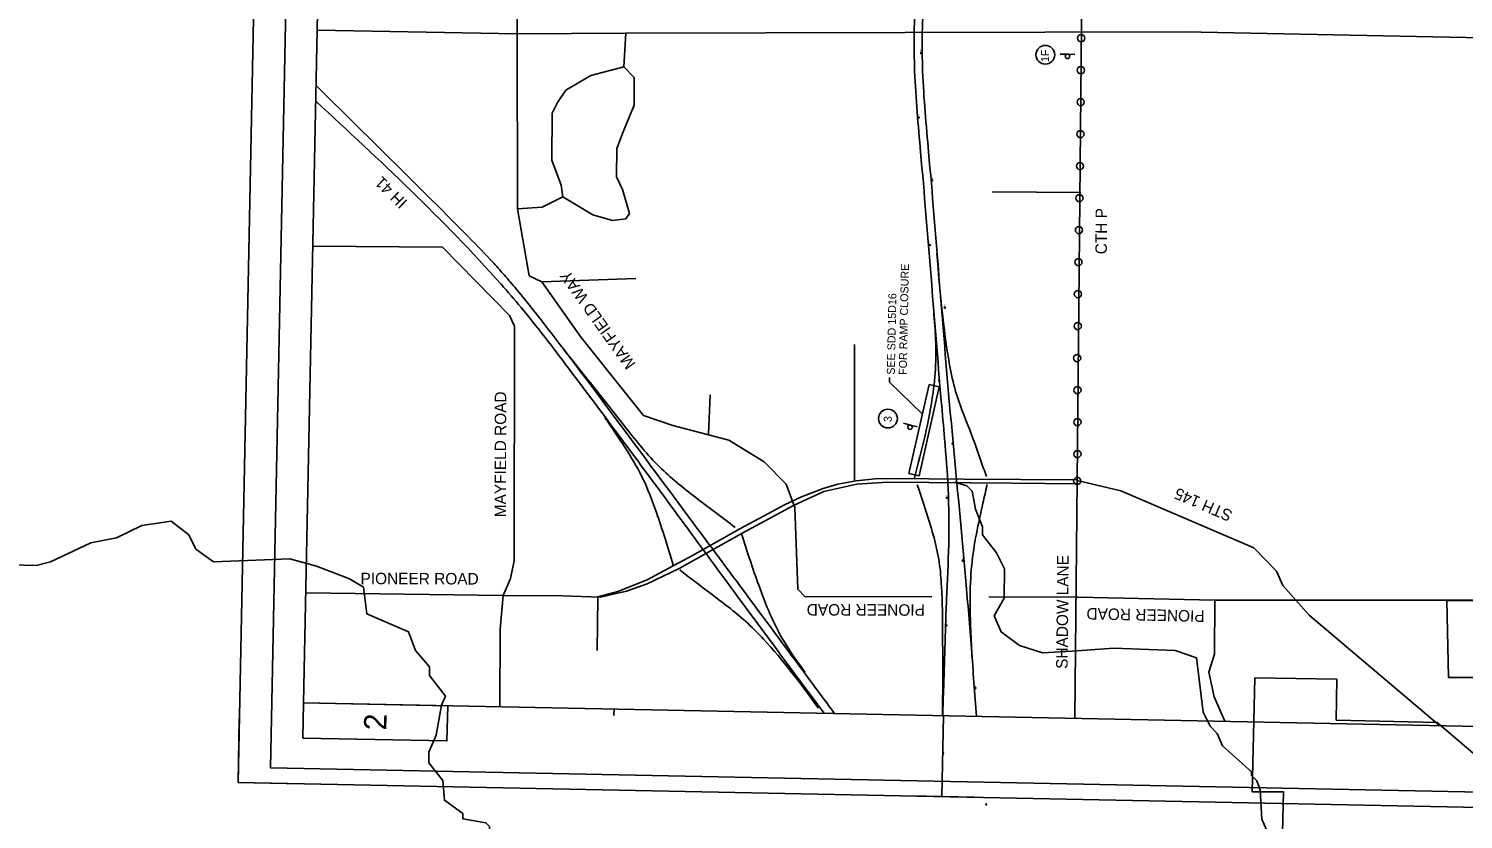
# Model space of a CAD drawing. Extents: x 331323 to 388339, y 121519 to 205315.
# Drawn here: x 352829 to 366276, y 130182 to 137595 of the extents above; entities that cross this region are included whole.
import ezdxf

# ---------------------------------------------------------------- set-up
doc = ezdxf.new("R2010")
doc.units = 0
for name, color, linetype in [('CA-TEXT', 7, 'Continuous'), ('CE-TOPO-CONC-SLAB', 7, 'Continuous'), ('E_SOIL_BORE1 [KAPUR_CADDS_LEVELS]', 7, 'Continuous'), ('E_SOIL_BORE2 [KAPUR_CADDS_LEVELS]', 7, 'Continuous'), ('Level 2', 7, 'Continuous'), ('Level 21', 7, 'Continuous'), ('Level 3', 7, 'Continuous'), ('Level 4', 7, 'Continuous'), ('Level 57', 7, 'Continuous'), ('P_MARK', 7, 'Continuous'), ('P_RDWY_Text', 7, 'Continuous'), ('P_TC', 7, 'Continuous'), ('PLT_Sheet_Border', 7, 'Continuous'), ('PLT_Sheet_Info', 7, 'Continuous'), ('SIGNS-POLES', 7, 'Continuous')]:
    doc.layers.add(name, color=color, linetype=linetype)

msp = doc.modelspace()

# ---------------------------------------------------------------- linework, layer by layer
at = {"layer": 'CA-TEXT'}
for p, q in [((360898, 134282), (360898, 134325)), ((361206, 133982), (360898, 134282))]:
    msp.add_line(p, q, dxfattribs=at)
for centre in [(362358, 137350), (360883, 133939)]:
    msp.add_circle(centre, 88, dxfattribs=at)
at = {"layer": 'CE-TOPO-CONC-SLAB'}
for centre in [(362694, 137506), (362691, 137206), (362689, 136906), (362687, 136606), (362683, 136306), (362678, 136006), (362673, 135706), (362668, 135406), (362663, 135106), (362662, 134806), (362656, 134506), (362659, 134206), (362659, 133906), (362659, 133606), (362657, 133355)]:
    msp.add_circle(centre, 33.5, dxfattribs=at)
at = {"layer": 'Level 2'}
msp.add_lwpolyline([(362657, 133360), (363065, 133262), (364311, 132726), (364526, 132507), (364583, 132373), (364830, 132096), (366052, 131060)], dxfattribs=at)
for points in [[(361414, 133750), (361383, 134102), (361189, 136437), (361133, 137194), (361147, 137923), (361252, 138764), (361336, 139462), (361400, 139990)], [(361712, 131147), (361665, 131783), (361613, 132419), (361458, 134102), (361264, 136437), (361208, 137193), (361223, 137922), (361327, 138763), (361411, 139462), (361475, 139988)], [(355523, 137061), (356920, 135674), (357158, 135428), (357273, 135300), (357385, 135170), (357696, 134781), (358305, 133974), (358999, 133039), (360250, 131353), (360382, 131174)], [(360285, 131176), (359489, 132250), (358879, 133080), (357889, 134411), (357444, 134981), (357256, 135199), (355520, 136915)], [(361805, 133396), (361649, 133834), (361517, 134194), (361461, 134443), (361342, 135488)], [(361306, 135014), (361331, 134477), (361306, 134184), (361132, 133383)], [(359452, 132917), (359056, 133218), (358722, 133506), (358408, 133877), (357848, 134581)], [(358229, 133950), (358416, 133670), (358577, 133393), (358713, 133057), (358871, 132569)], [(361414, 133750), (361447, 133280), (361452, 132761), (361432, 132242), (361414, 131698), (361396, 131154)], [(361158, 133317), (361307, 132849), (361359, 132621), (361374, 132505), (361383, 132388), (361391, 132223), (361394, 132058), (361395, 131154)], [(361672, 131684), (361653, 132234), (361668, 132565), (361773, 133147), (361813, 133322)], [(360104, 131562), (359906, 131854), (359672, 132376), (359512, 132851)], [(358931, 132520), (359213, 132305), (359550, 132036), (359716, 131872), (360232, 131224)]]:
    msp.add_spline(points, degree=3, dxfattribs=at)
at = {"layer": 'Level 21'}
msp.add_lwpolyline([(377063, 130598), (375063, 130636), (375076, 132102), (370943, 132185), (370895, 130740), (370392, 130742), (370319, 126443), (367795, 126431), (367808, 132231), (366120, 132233), (366136, 131513), (366392, 131512), (366390, 130783), (366031, 131091), (365085, 131112), (365090, 131495), (364323, 131507), (364297, 130440), (364589, 130440), (364573, 129673), (363929, 129678), (363912, 128375), (362626, 128410), (362594, 121807)], dxfattribs=at)
at = {"layer": 'Level 3'}
msp.add_lwpolyline([(362673, 142845), (362696, 137641), (362657, 133360)], dxfattribs=at)
at = {"layer": 'Level 4'}
for p, q in [((361860, 136065), (362690, 136059)), ((360569, 133362), (360568, 134634)), ((359200, 133793), (359216, 134161)), ((358163, 132260), (358158, 131766))]:
    msp.add_line(p, q, dxfattribs=at)
for points in [[(357407, 148129), (357408, 137547)], [(355533, 137580), (357408, 137547)], [(358426, 137554), (363663, 137565), (367234, 137492)], [(357408, 137547), (358426, 137554)], [(357408, 137547), (357410, 135905)], [(358406, 137238), (358426, 137554)], [(357836, 136018), (357820, 136126), (357731, 136361), (357735, 136802), (357786, 136902), (357862, 137018), (358097, 137157), (358406, 137238)], [(357836, 136018), (358118, 135849), (358301, 135797), (358426, 135813), (358460, 135862), (358395, 136088), (358338, 136205), (358341, 136472), (358366, 136538), (358400, 136629), (358503, 136879), (358505, 137137), (358406, 137238)], [(357410, 135905), (357643, 135920), (357836, 136018)], [(357410, 135905), (357521, 135279), (357637, 135220)], [(355492, 135556), (356706, 135545), (357334, 134906), (357383, 134805), (357379, 132605), (357344, 132439), (357276, 132281)], [(357637, 135220), (358521, 135253)], [(357637, 135220), (358007, 134700), (358428, 134171), (358593, 133969), (358867, 133875), (359391, 133737), (359723, 133534), (359929, 133324), (360011, 133106), (360037, 132340), (360103, 132272), (361293, 132269)], [(357276, 132281), (357836, 132276), (358185, 132264), (358433, 132320), (358627, 132391), (358925, 132532), (359524, 132868), (360005, 133126), (360281, 133254), (360592, 133324), (360880, 133342), (362050, 133333), (362657, 133328)], [(362658, 133365), (361593, 133372), (360937, 133376), (360764, 133375), (360586, 133356), (360414, 133323), (360275, 133283), (360072, 133206), (359920, 133134), (359717, 133023), (359495, 132906), (359051, 132655), (358743, 132490), (358625, 132428), (358351, 132318), (358164, 132268)], [(362636, 131129), (362657, 133360)], [(355427, 132304), (357276, 132281)], [(357276, 132281), (357248, 131965), (357245, 131237)], [(361829, 132268), (362664, 132266)], [(362664, 132266), (363948, 132237)], [(363948, 132237), (363943, 131729), (363891, 131563), (363939, 131329), (364039, 131101)], [(363948, 132237), (367128, 132236)]]:
    msp.add_lwpolyline(points, dxfattribs=at)
at = {"layer": 'Level 57'}
for points in [[(361506, 133343), (361622, 133309), (361672, 133258), (361704, 133091), (361769, 132924), (361768, 132849), (361900, 132681), (361974, 132530), (361971, 132255), (361878, 132090), (361943, 131939), (362117, 131812), (362333, 131744), (362609, 131758), (363001, 131788), (363576, 131766), (363776, 131697), (363838, 131188), (363903, 131054), (363969, 130987), (364018, 130870), (364291, 130626), (364291, 130593), (364341, 130542), (364373, 130459), (364387, 130183), (364469, 129999)], [(351966, 132588), (352900, 132562), (353034, 132595), (353411, 132775), (353653, 132822), (353888, 132937), (354163, 132976), (354329, 132850), (354394, 132716), (354560, 132597), (355278, 132624), (355527, 132555), (355835, 132436), (355967, 132360), (355998, 132109), (356389, 131939), (356454, 131764), (356586, 131612), (356585, 131529), (356734, 131336), (356699, 131253), (356647, 130970), (356579, 130812), (356578, 130712), (356710, 130545), (356725, 130361), (356899, 130235), (356898, 130185)], [(356898, 130185), (357115, 130149), (357148, 130116), (357162, 129882), (357237, 129815), (357470, 129829), (357720, 129827), (358061, 129716), (358317, 129413), (358466, 129329), (358908, 129266), (359024, 129182), (359258, 129196), (359783, 129208), (361568, 129209)]]:
    msp.add_lwpolyline(points, dxfattribs=at)
at = {"layer": 'P_MARK'}
for p, q in [((361188, 137365), (361198, 137365)), ((361193, 137370), (361193, 137360)), ((361168, 136761), (361178, 136761)), ((361173, 136766), (361173, 136756)), ((361291, 136173), (361301, 136173)), ((361296, 136178), (361296, 136168)), ((361273, 135566), (361283, 135566)), ((361278, 135571), (361278, 135561)), ((361411, 134979), (361421, 134979)), ((361416, 134984), (361416, 134974)), ((361358, 134294), (361368, 134294)), ((361363, 134299), (361363, 134289)), ((361484, 133704), (361494, 133704)), ((361489, 133709), (361489, 133699)), ((361430, 133197), (361440, 133197)), ((361435, 133202), (361435, 133192)), ((361580, 132607), (361590, 132607)), ((361585, 132612), (361585, 132602)), ((361427, 132000), (361437, 132000)), ((361432, 132005), (361432, 131995)), ((361697, 131413), (361707, 131413)), ((361702, 131418), (361702, 131408)), ((361396, 130801), (361406, 130801)), ((361401, 130806), (361401, 130796)), ((361799, 130321), (361809, 130321)), ((361804, 130326), (361804, 130316))]:
    msp.add_line(p, q, dxfattribs=at)
for centre in [(361193, 137365), (361173, 136761), (361296, 136173), (361278, 135566), (361416, 134979), (361363, 134294), (361489, 133704), (361435, 133197), (361585, 132607), (361432, 132000), (361702, 131413), (361401, 130801), (361804, 130321)]:
    msp.add_circle(centre, 5, dxfattribs=at)
for centre, radius, start, end in [((361193, 137365), 4.5, 89.9869, 179.9869), ((361193, 137365), 4, 89.9869, 179.9869), ((361193, 137365), 3.5, 89.9869, 179.9869), ((361193, 137365), 3, 89.9869, 179.9869), ((361193, 137365), 2.5, 89.9869, 179.9869), ((361193, 137365), 2, 89.9869, 179.9869), ((361193, 137365), 1.5, 89.9869, 179.9869), ((361193, 137365), 1, 89.9869, 179.9869), ((361193, 137365), 0.5, 89.9869, 179.9869), ((361193, 137365), 4.5, 269.9869, 359.9869), ((361193, 137365), 4, 269.9869, 359.9869), ((361193, 137365), 3.5, 269.9869, 359.9869), ((361193, 137365), 3, 269.9869, 359.9869), ((361193, 137365), 2.5, 269.9869, 359.9869), ((361193, 137365), 2, 269.9869, 359.9869), ((361193, 137365), 1.5, 269.9869, 359.9869), ((361193, 137365), 1, 269.9869, 359.9869), ((361193, 137365), 0.5, 269.9869, 359.9869), ((361173, 136761), 4.5, 89.9869, 179.9869), ((361173, 136761), 4, 89.9869, 179.9869), ((361173, 136761), 3.5, 89.9869, 179.9869), ((361173, 136761), 3, 89.9869, 179.9869), ((361173, 136761), 2.5, 89.9869, 179.9869), ((361173, 136761), 2, 89.9869, 179.9869), ((361173, 136761), 1.5, 89.9869, 179.9869), ((361173, 136761), 1, 89.9869, 179.9869), ((361173, 136761), 0.5, 89.9869, 179.9869), ((361173, 136761), 4.5, 269.9869, 359.9869), ((361173, 136761), 4, 269.9869, 359.9869), ((361173, 136761), 3.5, 269.9869, 359.9869), ((361173, 136761), 3, 269.9869, 359.9869), ((361173, 136761), 2.5, 269.9869, 359.9869), ((361173, 136761), 2, 269.9869, 359.9869), ((361173, 136761), 1.5, 269.9869, 359.9869), ((361173, 136761), 1, 269.9869, 359.9869), ((361173, 136761), 0.5, 269.9869, 359.9869), ((361296, 136173), 4.5, 89.9869, 179.9869), ((361296, 136173), 4, 89.9869, 179.9869), ((361296, 136173), 3.5, 89.9869, 179.9869), ((361296, 136173), 3, 89.9869, 179.9869), ((361296, 136173), 2.5, 89.9869, 179.9869), ((361296, 136173), 2, 89.9869, 179.9869), ((361296, 136173), 1.5, 89.9869, 179.9869), ((361296, 136173), 1, 89.9869, 179.9869), ((361296, 136173), 0.5, 89.9869, 179.9869), ((361296, 136173), 4.5, 269.9869, 359.9869), ((361296, 136173), 4, 269.9869, 359.9869), ((361296, 136173), 3.5, 269.9869, 359.9869), ((361296, 136173), 3, 269.9869, 359.9869), ((361296, 136173), 2.5, 269.9869, 359.9869), ((361296, 136173), 2, 269.9869, 359.9869), ((361296, 136173), 1.5, 269.9869, 359.9869), ((361296, 136173), 1, 269.9869, 359.9869), ((361296, 136173), 0.5, 269.9869, 359.9869), ((361278, 135566), 4.5, 89.9869, 179.9869), ((361278, 135566), 4, 89.9869, 179.9869), ((361278, 135566), 3.5, 89.9869, 179.9869), ((361278, 135566), 3, 89.9869, 179.9869), ((361278, 135566), 2.5, 89.9869, 179.9869), ((361278, 135566), 2, 89.9869, 179.9869), ((361278, 135566), 1.5, 89.9869, 179.9869), ((361278, 135566), 1, 89.9869, 179.9869), ((361278, 135566), 0.5, 89.9869, 179.9869), ((361278, 135566), 4.5, 269.9869, 359.9869), ((361278, 135566), 4, 269.9869, 359.9869), ((361278, 135566), 3.5, 269.9869, 359.9869), ((361278, 135566), 3, 269.9869, 359.9869), ((361278, 135566), 2.5, 269.9869, 359.9869), ((361278, 135566), 2, 269.9869, 359.9869), ((361278, 135566), 1.5, 269.9869, 359.9869), ((361278, 135566), 1, 269.9869, 359.9869), ((361278, 135566), 0.5, 269.9869, 359.9869), ((361416, 134979), 4.5, 89.9869, 179.9869), ((361416, 134979), 4, 89.9869, 179.9869), ((361416, 134979), 3.5, 89.9869, 179.9869), ((361416, 134979), 3, 89.9869, 179.9869), ((361416, 134979), 2.5, 89.9869, 179.9869), ((361416, 134979), 2, 89.9869, 179.9869), ((361416, 134979), 1.5, 89.9869, 179.9869), ((361416, 134979), 1, 89.9869, 179.9869), ((361416, 134979), 0.5, 89.9869, 179.9869), ((361416, 134979), 4.5, 269.9869, 359.9869), ((361416, 134979), 4, 269.9869, 359.9869), ((361416, 134979), 3.5, 269.9869, 359.9869), ((361416, 134979), 3, 269.9869, 359.9869), ((361416, 134979), 2.5, 269.9869, 359.9869), ((361416, 134979), 2, 269.9869, 359.9869), ((361416, 134979), 1.5, 269.9869, 359.9869), ((361416, 134979), 1, 269.9869, 359.9869), ((361416, 134979), 0.5, 269.9869, 359.9869), ((361363, 134294), 4.5, 89.9869, 179.9869), ((361363, 134294), 4, 89.9869, 179.9869), ((361363, 134294), 3.5, 89.9869, 179.9869), ((361363, 134294), 3, 89.9869, 179.9869), ((361363, 134294), 2.5, 89.9869, 179.9869), ((361363, 134294), 2, 89.9869, 179.9869), ((361363, 134294), 1.5, 89.9869, 179.9869), ((361363, 134294), 1, 89.9869, 179.9869), ((361363, 134294), 0.5, 89.9869, 179.9869), ((361363, 134294), 4.5, 269.9869, 359.9869), ((361363, 134294), 4, 269.9869, 359.9869), ((361363, 134294), 3.5, 269.9869, 359.9869), ((361363, 134294), 3, 269.9869, 359.9869), ((361363, 134294), 2.5, 269.9869, 359.9869), ((361363, 134294), 2, 269.9869, 359.9869), ((361363, 134294), 1.5, 269.9869, 359.9869), ((361363, 134294), 1, 269.9869, 359.9869), ((361363, 134294), 0.5, 269.9869, 359.9869), ((361489, 133704), 4.5, 89.9869, 179.9869), ((361489, 133704), 4, 89.9869, 179.9869), ((361489, 133704), 3.5, 89.9869, 179.9869), ((361489, 133704), 3, 89.9869, 179.9869), ((361489, 133704), 2.5, 89.9869, 179.9869), ((361489, 133704), 2, 89.9869, 179.9869), ((361489, 133704), 1.5, 89.9869, 179.9869), ((361489, 133704), 1, 89.9869, 179.9869), ((361489, 133704), 0.5, 89.9869, 179.9869), ((361489, 133704), 4.5, 269.9869, 359.9869), ((361489, 133704), 4, 269.9869, 359.9869), ((361489, 133704), 3.5, 269.9869, 359.9869), ((361489, 133704), 3, 269.9869, 359.9869), ((361489, 133704), 2.5, 269.9869, 359.9869), ((361489, 133704), 2, 269.9869, 359.9869), ((361489, 133704), 1.5, 269.9869, 359.9869), ((361489, 133704), 1, 269.9869, 359.9869), ((361489, 133704), 0.5, 269.9869, 359.9869), ((361435, 133197), 4.5, 89.9869, 179.9869), ((361435, 133197), 4, 89.9869, 179.9869), ((361435, 133197), 3.5, 89.9869, 179.9869), ((361435, 133197), 3, 89.9869, 179.9869), ((361435, 133197), 2.5, 89.9869, 179.9869), ((361435, 133197), 2, 89.9869, 179.9869), ((361435, 133197), 1.5, 89.9869, 179.9869), ((361435, 133197), 1, 89.9869, 179.9869), ((361435, 133197), 0.5, 89.9869, 179.9869), ((361435, 133197), 4.5, 269.9869, 359.9869), ((361435, 133197), 4, 269.9869, 359.9869), ((361435, 133197), 3.5, 269.9869, 359.9869), ((361435, 133197), 3, 269.9869, 359.9869), ((361435, 133197), 2.5, 269.9869, 359.9869), ((361435, 133197), 2, 269.9869, 359.9869), ((361435, 133197), 1.5, 269.9869, 359.9869), ((361435, 133197), 1, 269.9869, 359.9869), ((361435, 133197), 0.5, 269.9869, 359.9869), ((361585, 132607), 4.5, 89.9869, 179.9869), ((361585, 132607), 4, 89.9869, 179.9869), ((361585, 132607), 3.5, 89.9869, 179.9869), ((361585, 132607), 3, 89.9869, 179.9869), ((361585, 132607), 2.5, 89.9869, 179.9869), ((361585, 132607), 2, 89.9869, 179.9869), ((361585, 132607), 1.5, 89.9869, 179.9869), ((361585, 132607), 1, 89.9869, 179.9869), ((361585, 132607), 0.5, 89.9869, 179.9869), ((361585, 132607), 4.5, 269.9869, 359.9869), ((361585, 132607), 4, 269.9869, 359.9869), ((361585, 132607), 3.5, 269.9869, 359.9869), ((361585, 132607), 3, 269.9869, 359.9869), ((361585, 132607), 2.5, 269.9869, 359.9869), ((361585, 132607), 2, 269.9869, 359.9869), ((361585, 132607), 1.5, 269.9869, 359.9869), ((361585, 132607), 1, 269.9869, 359.9869), ((361585, 132607), 0.5, 269.9869, 359.9869), ((361432, 132000), 4.5, 89.9869, 179.9869), ((361432, 132000), 4, 89.9869, 179.9869), ((361432, 132000), 3.5, 89.9869, 179.9869), ((361432, 132000), 3, 89.9869, 179.9869), ((361432, 132000), 2.5, 89.9869, 179.9869), ((361432, 132000), 2, 89.9869, 179.9869), ((361432, 132000), 1.5, 89.9869, 179.9869), ((361432, 132000), 1, 89.9869, 179.9869), ((361432, 132000), 0.5, 89.9869, 179.9869), ((361432, 132000), 4.5, 269.9869, 359.9869), ((361432, 132000), 4, 269.9869, 359.9869), ((361432, 132000), 3.5, 269.9869, 359.9869), ((361432, 132000), 3, 269.9869, 359.9869), ((361432, 132000), 2.5, 269.9869, 359.9869), ((361432, 132000), 2, 269.9869, 359.9869), ((361432, 132000), 1.5, 269.9869, 359.9869), ((361432, 132000), 1, 269.9869, 359.9869), ((361432, 132000), 0.5, 269.9869, 359.9869), ((361702, 131413), 4.5, 89.9869, 179.9869), ((361702, 131413), 4, 89.9869, 179.9869), ((361702, 131413), 3.5, 89.9869, 179.9869), ((361702, 131413), 3, 89.9869, 179.9869), ((361702, 131413), 2.5, 89.9869, 179.9869), ((361702, 131413), 2, 89.9869, 179.9869), ((361702, 131413), 1.5, 89.9869, 179.9869), ((361702, 131413), 1, 89.9869, 179.9869), ((361702, 131413), 4.5, 269.9869, 359.9869), ((361702, 131413), 4, 269.9869, 359.9869), ((361702, 131413), 3.5, 269.9869, 359.9869), ((361702, 131413), 3, 269.9869, 359.9869), ((361702, 131413), 2.5, 269.9869, 359.9869), ((361702, 131413), 2, 269.9869, 359.9869), ((361702, 131413), 1.5, 269.9869, 359.9869), ((361702, 131413), 1, 269.9869, 359.9869), ((361702, 131413), 0.5, 269.9869, 359.9869), ((361702, 131413), 0.5, 89.9869, 179.9869), ((361401, 130801), 4.5, 89.9869, 179.9869), ((361401, 130801), 4, 89.9869, 179.9869), ((361401, 130801), 3.5, 89.9869, 179.9869), ((361401, 130801), 3, 89.9869, 179.9869), ((361401, 130801), 2.5, 89.9869, 179.9869), ((361401, 130801), 2, 89.9869, 179.9869), ((361401, 130801), 1.5, 89.9869, 179.9869), ((361401, 130801), 1, 89.9869, 179.9869), ((361401, 130801), 0.5, 89.9869, 179.9869), ((361401, 130801), 4.5, 269.9869, 359.9869), ((361401, 130801), 4, 269.9869, 359.9869), ((361401, 130801), 3.5, 269.9869, 359.9869), ((361401, 130801), 3, 269.9869, 359.9869), ((361401, 130801), 2.5, 269.9869, 359.9869), ((361401, 130801), 2, 269.9869, 359.9869), ((361401, 130801), 1.5, 269.9869, 359.9869), ((361401, 130801), 1, 269.9869, 359.9869), ((361401, 130801), 0.5, 269.9869, 359.9869), ((361804, 130321), 4.5, 89.9869, 179.9869), ((361804, 130321), 4, 89.9869, 179.9869), ((361804, 130321), 3.5, 89.9869, 179.9869), ((361804, 130321), 3, 89.9869, 179.9869), ((361804, 130321), 2.5, 89.9869, 179.9869), ((361804, 130321), 2, 89.9869, 179.9869), ((361804, 130321), 1.5, 89.9869, 179.9869), ((361804, 130321), 1, 89.9869, 179.9869), ((361804, 130321), 4.5, 269.9869, 359.9869), ((361804, 130321), 4, 269.9869, 359.9869), ((361804, 130321), 3.5, 269.9869, 359.9869), ((361804, 130321), 3, 269.9869, 359.9869), ((361804, 130321), 2.5, 269.9869, 359.9869), ((361804, 130321), 2, 269.9869, 359.9869), ((361804, 130321), 1.5, 269.9869, 359.9869), ((361804, 130321), 1, 269.9869, 359.9869), ((361804, 130321), 0.5, 269.9869, 359.9869), ((361804, 130321), 0.5, 89.9869, 179.9869)]:
    msp.add_arc(centre, radius, start, end, dxfattribs=at)
at = {"layer": 'P_RDWY_Text'}
msp.add_lwpolyline([(354791, 130528), (355202, 150924), (368399, 150658), (367988, 130262)], close=True, dxfattribs=at)
at = {"layer": 'P_TC'}
for p, q in [((361269, 134259), (361079, 133424)), ((361174, 133403), (361364, 134237)), ((361364, 134237), (361269, 134259)), ((361079, 133424), (361174, 133403))]:
    msp.add_line(p, q, dxfattribs=at)
at = {"layer": 'PLT_Sheet_Border'}
for points in [[(367988, 130262), (368399, 150658), (355202, 150924), (354791, 130528)], [(367691, 130412), (368091, 150268), (355494, 150522), (355094, 130666)]]:
    msp.add_lwpolyline(points, close=True, dxfattribs=at)
at = {"layer": 'PLT_Sheet_Info'}
for p, q in [((355406, 131274), (355787, 150171)), ((361414, 131604), (361414, 131604)), ((367404, 131033), (355406, 131274)), ((354791, 130528), (354803, 131128)), ((358315, 131216), (358314, 131156)), ((361389, 130395), (361405, 131154)), ((355391, 130516), (354791, 130528)), ((361689, 130389), (361090, 130401))]:
    msp.add_line(p, q, dxfattribs=at)
msp.add_lwpolyline([(355406, 131274), (355399, 130944), (356749, 130917), (356756, 131247)], close=True, dxfattribs=at)
at = {"layer": 'SIGNS-POLES'}
for p, q in [((362498, 137357), (362565, 137356)), ((362566, 137355), (362633, 137354)), ((361028, 133895), (361093, 133878)), ((361093, 133878), (361158, 133861))]:
    msp.add_line(p, q, dxfattribs=at)
for centre in [(362566, 137335), (361089, 133858)]:
    msp.add_circle(centre, 20.9, dxfattribs=at)

# ---------------------------------------------------------------- texts
at = {"layer": 'CA-TEXT'}
for s, height, rotation, p in [('1F', 75, 88.8468, (362392, 137281)), ('IH 41', 108, 135.3496, (356386, 135975)), ('CTH P', 108, 89.7111, (362935, 135479)), ('MAYFIELD WAY', 108, 125.4677, (358523, 134451)), ('FOR RAMP CLOSURE', 75, 88.8468, (361059, 134348)), ('SEE SDD 15D16', 75, 88.8468, (360947, 134350)), ('MAYFIELD ROAD', 108, 89.9056, (357303, 133014)), ('3', 75, 88.8468, (360918, 133906)), ('STH 145', 108, 156.7129, (364122, 133069)), ('SHADOW LANE', 108, 89.4712, (362567, 131592)), ('PIONEER ROAD', 108, 359.8543, (355939, 132386)), ('PIONEER ROAD', 108, 179.8543, (361229, 132198)), ('PIONEER ROAD', 108, 178.7378, (363852, 132140))]:
    msp.add_text(s, height=height, rotation=rotation, dxfattribs=at).set_placement(p)
at = {"layer": 'E_SOIL_BORE1 [KAPUR_CADDS_LEVELS]'}
for s, p in [('B18', (361196, 137374)), ('B13', (361281, 135575)), ('B14', (361420, 134986)), ('B10', (361589, 132614)), ('B7', (361436, 132009)), ('B8', (361705, 131421))]:
    msp.add_text(s, height=10, rotation=89.9869, dxfattribs=at).set_placement(p)
at = {"layer": 'E_SOIL_BORE2 [KAPUR_CADDS_LEVELS]'}
for s, p in [('B18', (361198, 137372)), ('B15', (361175, 136769)), ('B16', (361301, 136180)), ('B11', (361366, 134304)), ('B12', (361493, 133710)), ('B9', (361439, 133206)), ('B5', (361404, 130809)), ('B6', (361807, 130327))]:
    msp.add_text(s, height=10, rotation=89.9869, dxfattribs=at).set_placement(p)
at = {"layer": 'PLT_Sheet_Info'}
msp.add_text('2', height=210, rotation=88.8462, dxfattribs=at).set_placement((356181, 131015))

doc.saveas('drawing.dxf')
